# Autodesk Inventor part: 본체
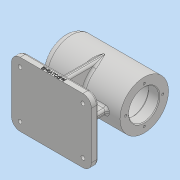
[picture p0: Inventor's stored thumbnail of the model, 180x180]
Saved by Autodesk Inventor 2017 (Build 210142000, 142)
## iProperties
Part Number: 본체
Material: 일반
Document SubType Name: Modeling
Designer: mrc
Density: 1 g/cm^3
Appearance: 기본값
Author: mrc
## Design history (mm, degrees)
sketch "스케치1"
  geometry: L1 (-56, 0)-(56, 0); L2 (-56, 0)-(-56, 34); L3 (-56, 34)-(56, 34); L4 (56, 34)-(56, 21); L5 (56, 21)-(41, 21); L6 (41, 21)-(41, 24); L7 (41, 24)-(-13, 24); L8 (-13, 24)-(-13, 21); L9 (-13, 21)-(-25, 21); L10 (-25, 21)-(-25, 17.5); L11 (-25, 17.5)-(-43, 17.5); L12 (-43, 17.5)-(-43, 16); L13 (-43, 16)-(-47, 16); L14 (-47, 16)-(-47, 10.5); L15 (-47, 10.5)-(-50, 10.5); L16 (-50, 10.5)-(-50, 0); 2 further points
  constraints: 32 end point, 14 perpendicular, 2 midpoint, 1 horizontal, 1 point on line, 1 vertical, 1 vertical alignment
  dimensions: "d0" = 68 diameter of L3 L1; "d1" = 112 distance between parallel lines of L4 L2; "d2" = 15 distance between parallel lines of L4 L6; "d3" = 54 distance between parallel lines of L8 L6; "d4" = 12 distance between parallel lines of L10 L8; "d5" = 18 distance between parallel lines of L12 L10; "d6" = 4 distance between parallel lines of L12 L14; "d7" = 3 distance between parallel lines of L16 L14; "d8" = 42 diameter of L5 L1; "d9" = 48 diameter of L7 L1; "d10" = 42 diameter of L9 L1; "d11" = 35 diameter of L11 L1; "d12" = 32 diameter of L13 L1; "d13" = 21 diameter of L15 L1
revolve "회전1" sketch "스케치1" stored, may be unused: angle "d14" = 90 deg
node "스케치2"
sketch "스케치3"
  geometry: 2 further points
  constraints: 1 vertical alignment
  dimensions: "d15" = 26 distance of point (0, 0) point (0, 26)
hole "구멍1" sketch "스케치3" at (0, 26) diameter "d16" = 3.242; stored, may be unused: countersink angle "d20" = 90 deg, drill point angle "d22" = 118 deg; dims "d17" = 8, "d18" = 4, "d19" = 2, "d21" = 11
node "작업 평면1"
sketch "스케치4"
  geometry: L1 (56, 45)-(-56, 45); L2 (-56, 45)-(-56, -45); L3 (-56, -45)-(56, -45); L4 (56, -45)-(56, 45); 3 further points
  constraints: 8 end point, 2 midpoint, 2 parallel, 1 horizontal, 1 horizontal alignment, 1 perpendicular, 1 vertical alignment
  dimensions: "d27" = 112 distance between parallel lines of L2 L4; "d28" = 90 distance between parallel lines of L3 L1
extrude "돌출1" join sketch "스케치4" distance "d29" = 10; taper "d30" = 0 deg
sketch "스케치5"
  geometry: L1 (-4, 34)-(4, 34); L2 (4, 34)-(4, -34); L3 (4, -34)-(-4, -34); L4 (-4, -34)-(-4, 34); L5 (-38, 4)-(38, 4); L6 (38, 4)-(38, -4); L7 (38, -4)-(-38, -4); L8 (-38, -4)-(-38, 4); L9 (56, -45)-(56, 45) reference; 5 further points
  constraints: 16 end point, 4 midpoint, 4 parallel, 2 horizontal, 2 horizontal alignment, 2 perpendicular, 2 vertical alignment
  dimensions: "d31" = 8 distance between parallel lines of L2 L4; "d32" = 8 distance between parallel lines of L7 L5; "d33" = 18 distance between parallel lines of L9 L6; "d34" = 68 distance between parallel lines of L3 L1
extrude "돌출2" join sketch "스케치5" stored distance "d35" = 10; taper "d36" = 0 deg
sketch "스케치6"
  geometry: L1 (112, 0)-(112, 10) reference; L2 (0, 0)-(112, 0) reference; 2 further points
  constraints: 1 other
  dimensions: "d37" = 56 distance from line of L1 point (56, 3); "d38" = 3 distance from line of L2 point (56, 3)
feature "엠보싱1" sketch "스케치6" dims "d0" = 68, "d1" = 112, "d2" = 15, "d3" = 54, "d4" = 12, "d5" = 18, "d6" = 4, "d7" = 3, "d8" = 42, "d9" = 48, "d10" = 42, "d11" = 35, "d12" = 32, "d13" = 21, "d39" = 0.5, "d40" = 0
fillet "모깎기1" dims "d41" = 12
sketch "스케치7"
  geometry: L1 (-56, 33)-(-56, -33) reference; L2 (44, 45)-(-44, 45) reference; L3 (56, -33)-(56, 33) reference; L4 (-44, -45)-(44, -45) reference; A1 r 12 centre (-44, -33) between (-56, -33) and (-44, -45) reference; A2 r 12 centre (-44, 33) between (-44, 45) and (-56, 33) reference; A3 r 12 centre (44, 33) between (56, 33) and (44, 45) reference; A4 r 12 centre (44, -33) between (44, -45) and (56, -33) reference; 5 further points
  constraints: 4 coincident
hole "구멍2" sketch "스케치7" at (-44, 33), (44, 33), (44, -33), (-44, -33) diameter "d42" = 5.5; stored, may be unused: countersink angle "d46" = 90 deg, drill point angle "d48" = 118 deg; dims "d43" = 8, "d44" = 9.5, "d45" = 5.4, "d47" = 11
chamfer "모따기1" distance "d49" = 1; stored, may be unused: second distance "d50" = 2, angle "d51" = 45 deg
fillet "모깎기2" dims "d52" = 3
fillet "모깎기3" dims "d53" = 3
fillet "모깎기4" dims "d54" = 0.3
fillet "모깎기5" dims "d55" = 3
fillet "모깎기6" dims "d56" = 3
fillet "모깎기7" dims "d57" = 3
fillet "모깎기8" dims "d58" = 3
fillet "모깎기9" dims "d59" = 3
fillet "모깎기10" dims "d60" = 10
fillet "모깎기11" dims "d61" = 3
node "솔리드1"
pattern_circular "원형 패턴1" dims angle "d24" = 360 deg
node "투영된 루프1"
other parameters: "d26" = -74
